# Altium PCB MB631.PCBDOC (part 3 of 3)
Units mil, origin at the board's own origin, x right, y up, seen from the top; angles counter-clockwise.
Board outline 4505 x 6805 mil, 4 copper layers (TopLayer, GND, VCC, BottomLayer); 273 components, 241 nets, 1286 pads, 636 vias.
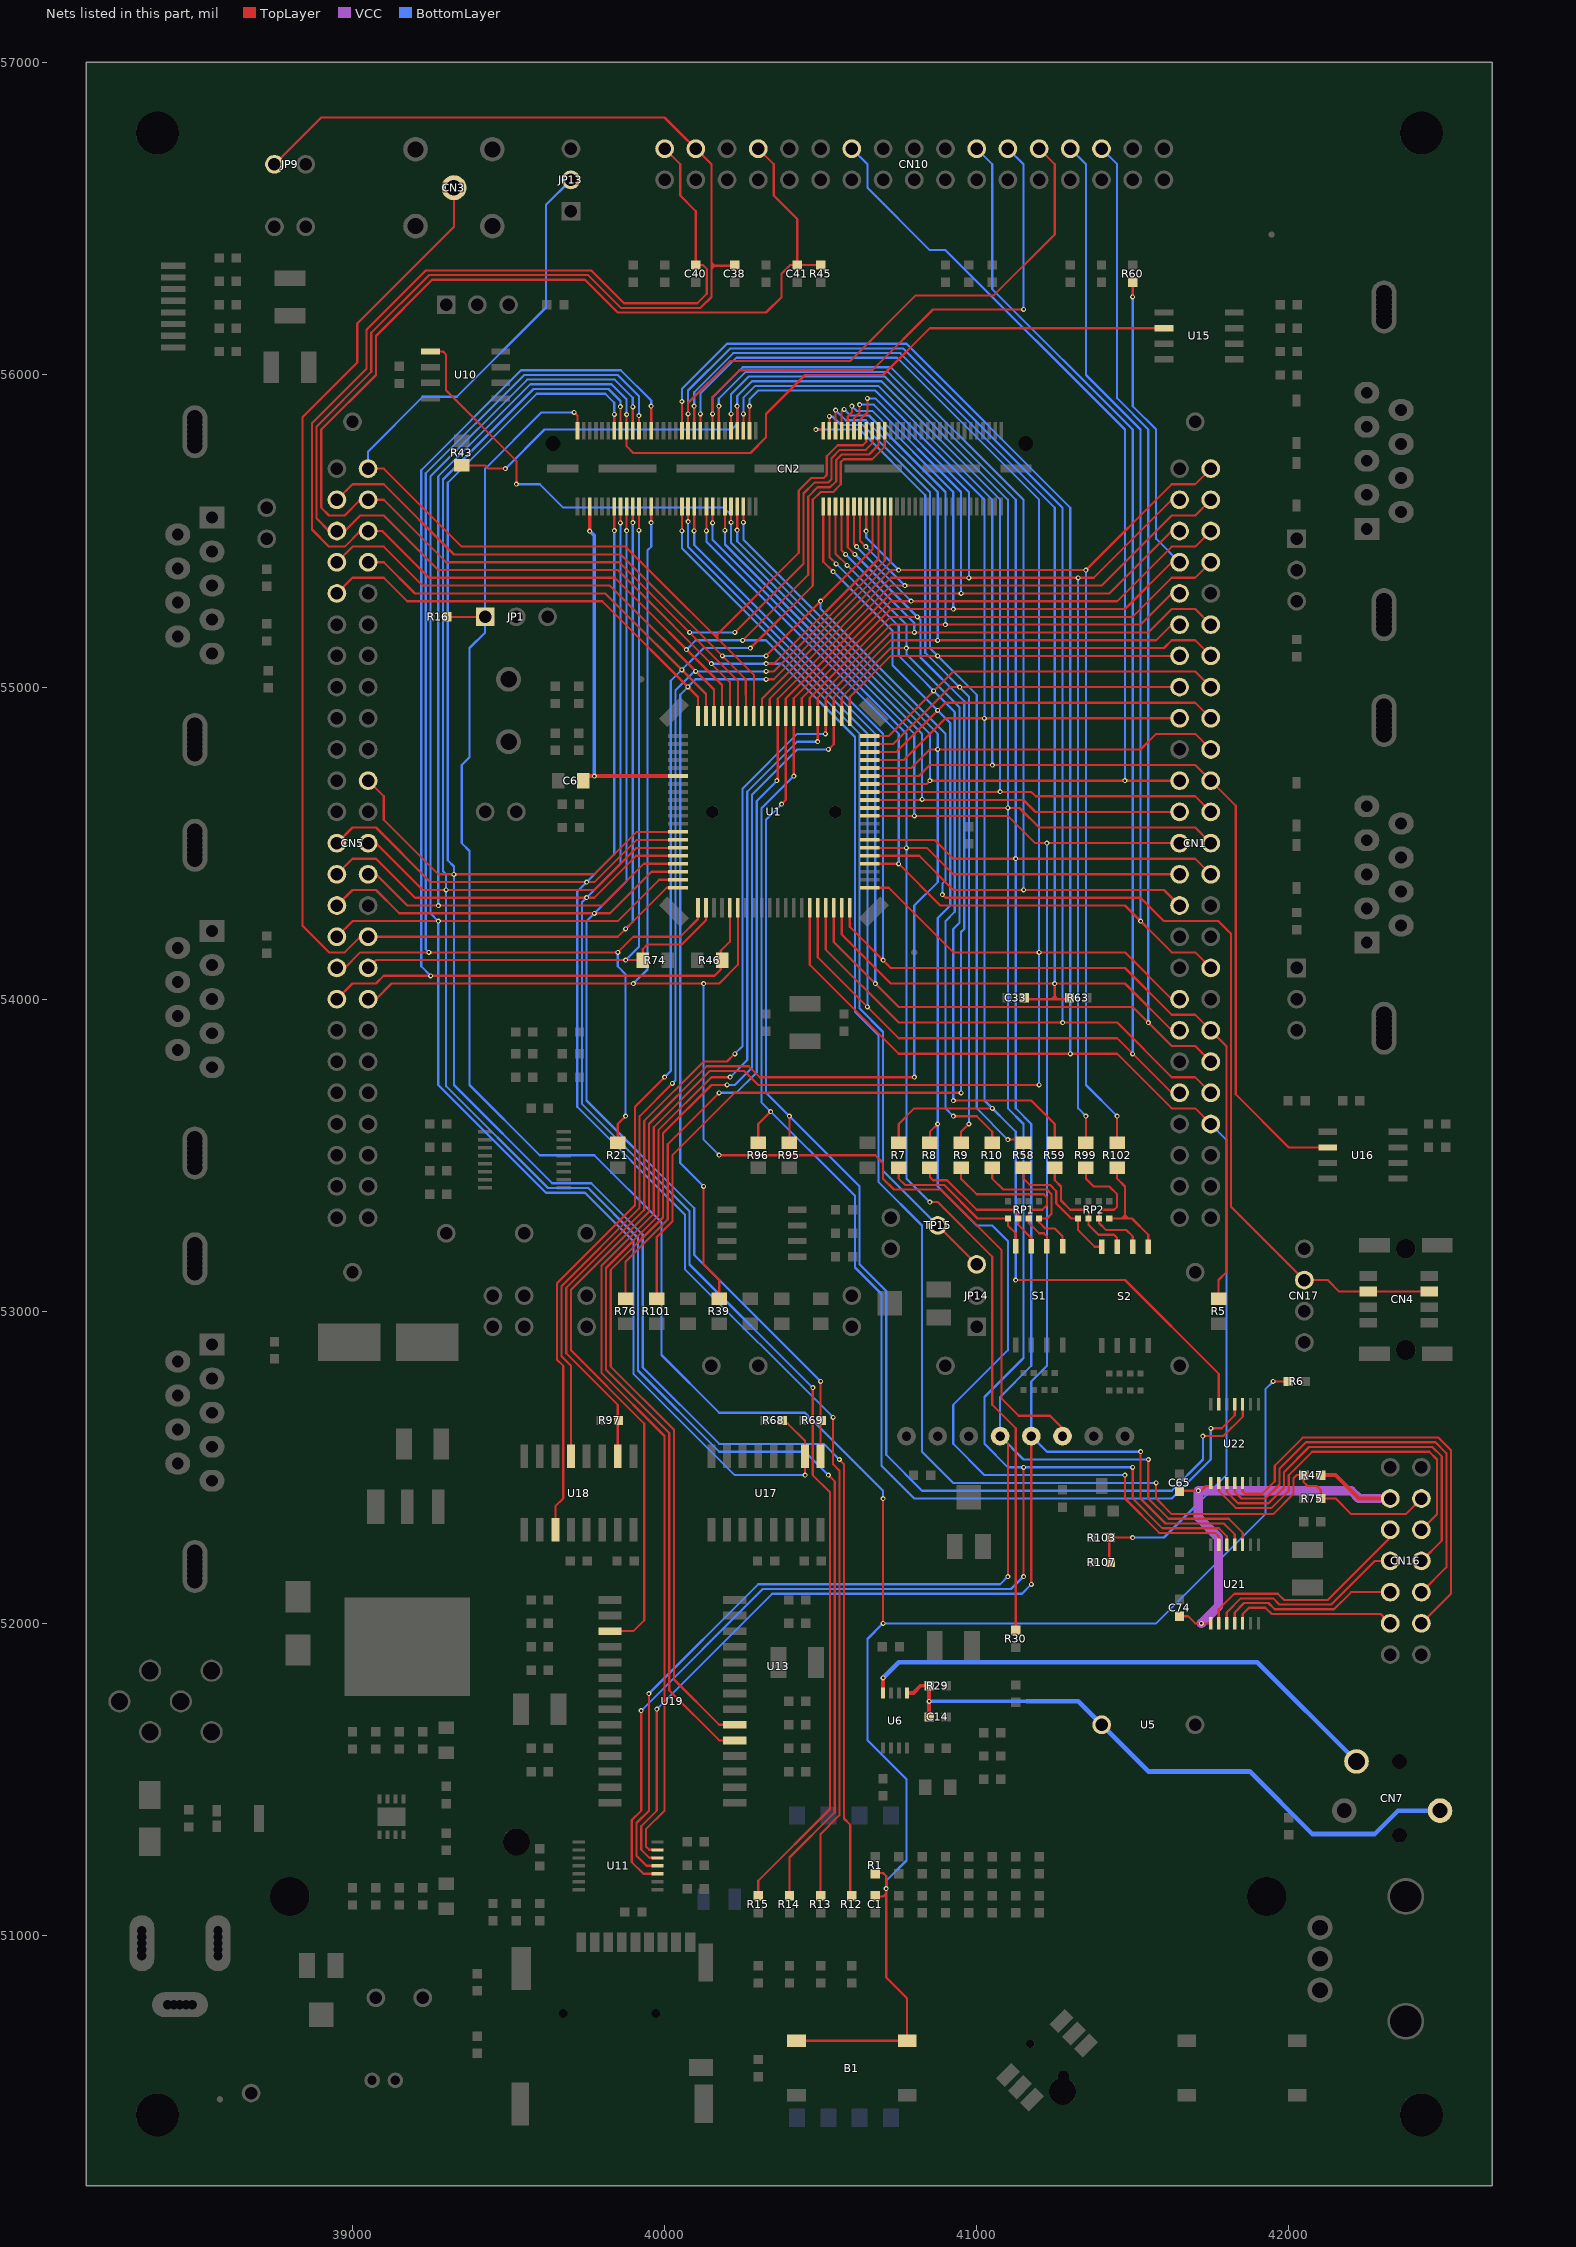
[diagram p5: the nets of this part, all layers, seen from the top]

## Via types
v1: diameter 16, hole 8, TopLayer to BottomLayer, tented both sides, 568 vias
v2: diameter 16, hole 8, TopLayer to BottomLayer, 68 vias

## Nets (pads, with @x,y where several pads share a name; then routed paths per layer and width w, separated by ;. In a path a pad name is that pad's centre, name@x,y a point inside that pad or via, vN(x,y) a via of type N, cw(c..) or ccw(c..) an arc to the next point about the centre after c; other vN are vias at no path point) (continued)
PC2: CN1.34 CN2.44 CN10.7 U1.44 | length 5197.9
  TopLayer w7: v1(40134.25,55500.75) CN2.44@40134.25,55578.54 ; U1.44@40657.09,54433.66 v1(40750,54433.66) 40883.66,54300 41475,54300 41625,54150 41700,54150 CN1.34@41750,54100
  BottomLayer w7: v1(40134.25,55500.75) 40134.25,55465.75 40750,54850 v1@40750,54435 ; CN10.7@41300,56725 41350,56675 41350,56000 41525,55825 v1(41525,54250)
PC3: CN1.29 CN2.45 CN10.11 U1.45 | length 5331
  TopLayer w7: CN2.45@40153.94,55821.46 40153.94,55930 40238.94,56015 40665,56015 40860,56210 v1(41150,56210) ; U1.45@40657.09,54459.25 40815.75,54459.25 40925,54350 41600,54350 CN1.29@41650,54300
  BottomLayer w7: v1(40153.94,55875) 40153.94,55928.94 40250,56025 40725,56025 41150,55600 v1(41150,54350) ; CN10.11@41100,56725 41150,56675 v1(41150,56210)
PC4: CN1.27 CN2.46 R30.1 U1.46 | length 5046
  TopLayer w7: v1(40153.94,55526.06) CN2.46@40153.94,55578.54 ; U1.46@40657.09,54484.84 40840.16,54484.84 40925,54400 CN1.27@41650,54400 ; v1(40850,53350) 40875,53350 41050,53175 41050,52700 41125,52625 R30.1@41125,51977.5
  BottomLayer w7: v1(40153.94,55526.06) 40153.94,55471.06 40775,54850 40775,53425 v1(40850,53350)
  other v1: 40775,54485
PC5: CN1.28 CN2.47 U1.47 U11.11 U13.4 U21.10 | length 8859.3
  TopLayer w7: v2(39950,51775) 39950,51400 39910,51360 39910,51255 39941.77,51223.23 U11.11@39976.97,51223.23 ; CN2.47@40173.62,55821.46 v1(40173.62,55900) ; U1.47@40657.09,54510.43 40864.57,54510.43 40925,54450 41700,54450 CN1.28@41750,54400 ; U13.4@41075,52600 41100,52575 v2(41100,52150) ; v2(41550,52525) 41550,52400 41615,52335 41807.36,52335 41852.36,52290 U21.10@41852.36,52251.97
  BottomLayer w7: v2(39950,51775) 40300,52125 41075,52125 v2(41100,52150) ; v1(40173.62,55900) 40173.62,55923.62 40260,56010 40715,56010 41125,55600 41125,53650 41175,53600 41175,52825 41075,52725 U13.4@41075,52600 41150,52525 v2(41550,52525)
  other v1: 41125,54450
PC6: CN1.25 CN2.50 U1.50 U11.12 U13.5 U21.11 | length 7469.7
  TopLayer w7: v2(39975,51725) 39975,51400 39925,51350 39925,51275 39951.18,51248.82 U11.12@39976.97,51248.82 ; v1(40193.31,55501.69) CN2.50@40193.31,55578.54 ; U1.50@40657.09,54587.2 41100,54587.2 41187.2,54500 CN1.25@41650,54500 ; v2(41175,52125) U13.5@41175,52600 ; v2(41525,52550) 41525,52400 41605,52320 41791.77,52320 41826.77,52285 U21.11@41826.77,52251.97
  BottomLayer w7: v2(39975,51725) 40345,52095 41145,52095 v2(41175,52125) ; v1(40193.31,55501.69) 40193.31,55456.69 40800,54850 v1(40800,54587.2) ; v1(41225,54500) 41225,52825 41175,52775 U13.5@41175,52600 41225,52550 v2(41525,52550)
PC7: CN1.26 CN2.51 U1.51 U11.10 U21.12 | length 8760.5
  TopLayer w7: v2(39925,51720) 39925,51400 39895,51370 39895,51235 39932.36,51197.64 U11.10@39976.97,51197.64 ; CN2.51@40212.99,55821.46 v1(40212.99,55875) ; U1.51@40657.09,54612.8 41137.2,54612.8 41200,54550 41700,54550 CN1.26@41750,54500 ; v2(41150,52150) v2(41150,52500) ; v2(41500,52500) 41500,52400 41595,52305 41775.59,52305 41801.18,52279.41 U21.12@41801.18,52251.97
  BottomLayer w7: v2(39925,51720) 40315,52110 41110,52110 v2(41150,52150) ; v1(40212.99,55875) 40212.99,55937.99 40270,55995 40705,55995 41100,55600 41100,53650 41150,53600 41150,52850 41025,52725 41025,52575 41100,52500 v2(41500,52500)
  other v1: 41100,54612.8
PD0: CN2.75 CN5.2 JP13.2 U1.73 | length 3859.2
  TopLayer w7: CN5.2@39050,55700 39100,55700 39350,55450 39875,55450 40286.02,55038.98 U1.73@40286.02,54907.09 ; 40154.87,55170.13 40170.13,55170.13 40170,55170 40170,55155 40169.76,55155.24 ; 40163.11,55163.11 40430,55430 40430,55630 40470,55670 40510,55670 40519.72,55679.72 40519.72,55739.72 40555,55775 40635,55775 40646.06,55786.06 CN2.75@40646.06,55821.46
  BottomLayer w7: CN5.2@39050,55700 39050,55755 39225,55930 39333.79,55930 39620,56216.21 39620,56545 JP13.2@39700,56625
PD1: CN2.78 CN4.2 CN5.3 CN17.2 U1.74 | length 6176.3
  TopLayer w7: CN5.3@38950,55600 39000,55650 39100,55650 39325,55425 39860,55425 40260,55025 40260,54975 ; U1.74@40260.43,54907.09 40260.43,54975 ; v1(40325,55100) 40665.75,55440.75 CN2.78@40665.75,55578.54 ; v1(40890,54335) 40900,54325 41525,54325 41600,54250 41775,54250 41815,54210 41815,53335 CN17.2@42050,53100 42125,53100 42162.01,53062.99 CN4.2@42449.8,53062.99
  BottomLayer w7: v1(40185,55100) v1(40325,55100) ; v1(40500,55275) 40500,55250 40900,54850 40900,54380 40890,54370 v1(40890,54335)
PD2: C41.2 CN2.77 CN5.4 CN10.27 R45.2 U1.75 | length 5464.8
  TopLayer w7: v1(40225,55175) 40445,55395 40445,55620 40480,55655 40523.79,55655 40534.72,55665.93 40534.72,55733.51 40561.21,55760 40645,55760 40665.75,55780.75 CN2.77@40665.75,55821.46 ; U1.75@40234.84,54907.09 40234.84,55020.16 39855,55400 39300,55400 39100,55600 39025,55600 38975,55550 38925,55550 38900,55575 38900,55825 39075,56000 39075,56125 39255,56305 39745,56305 39850,56200 40325,56200 40375,56250 40375,56325 40402.5,56352.5 R45.2@40500,56352.5 ; CN10.27@40300,56725 40350,56675 40350,56575 40425,56500 C41.2@40425,56352.5
  BottomLayer w7: v1(40080,55175) v1(40225,55175)
PD3: C38.2 CN2.80 CN5.5 CN10.31 CN16.11 JP9.1 R47.1 R75.2 U1.76 | length 11107.5
  TopLayer w7: JP9.1@38750,56675 38900,56825 40000,56825 40150,56675 40150,56250 40115,56215 39860,56215 39755,56320 39245,56320 39060,56135 39060,56010 38885,55835 38885,55540 38925,55500 CN5.5@38950,55500 ; CN5.5@38975,55500 39025,55550 39100,55550 39275,55375 39850,55375 40209.25,55015.75 U1.76@40209.25,54907.09 ; 40150,56340 40160,56350 40150,56360 ; 40150,56350 C38.2@40222.5,56350 ; v1(40325,55075) 40350,55075 40685.43,55410.43 CN2.80@40685.43,55578.54 ; v2(41575,52450) 41575,52400 41625,52350 41950,52350 42015,52415 42015,52465 42025,52475 R47.1@42047.5,52475 42047.5,52452.5 42060,52440 42090,52440 42102.5,52427.5 R75.2@42102.5,52400 42150,52400 42200,52350 42375,52350 CN16.11@42425,52400
  BottomLayer w7: v1(40150,55075) 40375,55075 40610,54840 40610,53960 40685,53885 40685,53415 40825,53275 40825,52550 40925,52450 v2(41575,52450)
PD4: C40.2 CN2.79 CN5.6 CN10.33 JP14.3 TP15.1 U1.77 | length 7605.7
  TopLayer w7: CN10.33@40000,56725 40050,56675 40050,56575 40100,56525 C40.2@40100,56352.5 40122.5,56352.5 40135,56340 40135,56260 40105,56230 39870,56230 39765,56335 39235,56335 39045,56145 39045,56020 38870,55845 38870,55505 38925,55450 38975,55450 39025,55500 39095,55500 39245,55350 39840,55350 40183.66,55006.34 U1.77@40183.66,54907.09 ; v1(40250,55150) 40460,55360 40460,55610 40490,55640 40530,55640 40549.72,55659.72 40549.72,55727.29 40567.43,55745 40655,55745 40685.43,55775.43 CN2.79@40685.43,55821.46 ; TP15.1@40875,53275 JP14.3@41000,53150
  BottomLayer w7: v1(40070,55120) 40100,55150 40325,55150 40625,54850 40625,53970 40700,53895 40700,53450 TP15.1@40875,53275
PD5: CN2.82 CN5.7 U1.78 U18.13 | length 5147.4
  TopLayer w7: CN5.7@38950,55400 39000,55450 39100,55450 39225,55325 39825,55325 40158.07,54991.93 U1.78@40158.07,54907.09 ; U18.13@39700,52525 39700,52825 39670,52855 39670,53081.21 39920,53331.21 39920,53625 v1(40025,53730) ; v1(40325,55050) 40350,55050 40705.12,55405.12 CN2.82@40705.12,55578.54
  BottomLayer w7: v1(40025,53730) 40035,53740 40035,54990 40095.17,55050.17 v1@40099.83,55050.17 ; v1@40100,55050 v1(40325,55050)
  other v1: 40099.49,55050.51
PD6: CN2.81 CN5.8 U1.79 U18.3 | length 5467.8
  TopLayer w7: CN5.8@39050,55400 39100,55400 39200,55300 39810,55300 40132.48,54977.52 U1.79@40132.48,54907.09 ; U18.3@39650,52300 39650,52375 39675,52400 39675,52825 39655,52845 39655,53090 39905,53340 39905,53655 v1(40000,53750) ; v1(40275,55125) 40475,55325 40475,55600 40500,55625 40540,55625 40564.72,55649.72 40564.72,55721.08 40573.64,55730 40665,55730 40705.12,55770.12 CN2.81@40705.12,55821.46
  BottomLayer w7: v1(40000,53750) 40020,53770 40020,55020 40125,55125 v1(40275,55125)
  other v1: 40055.41,55055.41
PD7: CN2.84 CN5.9 R39.2 U1.80 | length 4413.6
  TopLayer w7: CN5.9@38950,55300 39000,55350 39100,55350 39175,55275 39800,55275 40106.89,54968.11 U1.80@40106.89,54907.09 ; v1(40125,53400) 40125,53150 40175,53100 R39.2@40175,53040 ; v1(40325,55025) 40350,55025 40724.8,55399.8 CN2.84@40724.8,55578.54
  BottomLayer w7: v1(40125,53400) 40050,53475 40050,54975.81 40099.19,55025 v1(40325,55025)
  other v1: 40074.59,55000.41
PE0: CN1.4 CN2.74 R76.1 U1.70 | length 4121.2
  TopLayer w7: R76.1@39875,53040 39875,53158.93 40010,53293.93 40010,53535 v1(40175,53700) ; v1(40360,54700) 40362.8,54702.8 40362.8,54962.8 40725,55325 41400,55325 41625,55550 41700,55550 CN1.4@41750,55600 ; CN2.74@40626.38,55578.54 40626.38,55468.62 v1(40645,55450)
  BottomLayer w7: v1(40175,53700) 40230,53700 40295,53765 40295,54635 v1(40360,54700) ; v1(40645,55450) v1(40770,55325)
PE1: CN1.5 CN2.71 R95.1 U1.69 U22.10 | length 6407
  TopLayer w7: v1(40375,54625) 40388.39,54638.39 40388.39,54963.39 40725,55300 41425,55300 41625,55500 CN1.5@41650,55500 ; R95.1@40400,53540 v1(40400,53625) ; CN2.71@40606.69,55821.46 40606.69,55861.69 40625,55880 v1(40625,55905) ; v2(41725,52600) 41790,52600 41852.36,52662.36 U22.10@41852.36,52701.97
  BottomLayer w7: v1(40375,54625) 40325,54575 40325,53700 40625,53400 40625,53150 40710,53065 40710,52540 40825,52425 41625,52425 41725,52525 v2(41725,52600) ; v1(40625,55905) 40670,55905 40950,55625 v1(40950,55300)
PE2: CN1.6 CN2.72 R96.1 U1.68 U22.11 | length 6095.1
  TopLayer w7: R96.1@40300,53540 40300,53600 v1(40340,53640) ; v1(40413.98,54715) 40413.98,54963.98 40725,55275 41450,55275 41625,55450 41700,55450 CN1.6@41750,55500 ; CN2.72@40606.69,55578.54 40606.69,55458.31 v1(40615,55450) ; v2(41750,52625) 41785,52625 41826.77,52666.77 U22.11@41826.77,52701.97
  BottomLayer w7: v1(40413.98,54715) 40310,54611.02 40310,53670 40610,53370 40610,53140 40695,53055 40695,52505 40800,52400 41625,52400 41750,52525 v2(41750,52625) ; v1(40615,55450) v1(40790,55275)
PE3: CN1.7 CN2.69 R60.2 U1.67 | length 3305.7
  TopLayer w7: U1.67@40439.57,54907.09 40439.57,54964.57 40725,55250 41475,55250 41625,55400 CN1.7@41650,55400 ; CN2.69@40587.01,55821.46 40587.01,55867.01 40600,55880 v1(40600,55900) ; v1(41500,56250) R60.2@41500,56297.5
  BottomLayer w7: v1(40600,55900) 40615,55885 40665,55885 40925,55625 v1(40925,55250) ; v1(41500,56250) 41500,55900 41575,55825 41575,55475 CN1.7@41650,55400
PE4: CN1.8 CN2.70 R101.2 U1.66 | length 5048.8
  TopLayer w7: R101.2@39975,53040 39975,53237.72 40025,53287.72 40025,53500 40225,53700 v1(40950,53700) ; U1.66@40465.16,54907.09 40465.16,54965.16 40725,55225 41500,55225 41625,55350 41700,55350 CN1.8@41750,55400 ; CN2.70@40587.01,55578.54 40587.01,55447.99 v1(40610,55425)
  BottomLayer w7: v1(40610,55425) 40820,55215 40820,55095 40960,54955 40960,54225 40950,54215 v1(40950,53700)
  other v1: 40810,55225
PE5: CN1.35 CN2.41 U1.41 U11.13 | length 8308.2
  TopLayer w7: U11.13@39976.97,51274.41 39950.59,51274.41 39940,51285 39940,51340 40000,51400 40000,52600 39797.5,52802.5 39797.5,53145.07 39965,53312.57 39965,53590 40145,53770 40255,53770 40300,53725 v1(41200,53725) ; CN2.41@40114.57,55821.46 v1(40114.57,55875) ; U1.41@40657.09,54356.89 40718.11,54356.89 40925,54150 41475,54150 41625,54000 CN1.35@41650,54000
  BottomLayer w7: v1(40114.57,55875) 40114.57,55939.57 40230,56055 40745,56055 41200,55600 v1(41200,53725)
  other v1: 41200,54150
PE6: CN1.38 CN2.40 R5.1 U1.40 | length 3950.6
  TopLayer w7: v1(40094.88,55500.12) CN2.40@40094.88,55578.54 ; U1.40@40593.11,54292.91 40593.11,54231.89 40725,54100 41475,54100 41625,53950 41700,53950 41800,53850 41800,53125 41775,53100 R5.1@41775,53040
  BottomLayer w7: v1(40094.88,55500.12) 40094.88,55455.12 40700,54850 v1(40700,54125)
PE7: C33.2 CN1.37 CN2.39 R63.2 U1.39 | length 4554
  TopLayer w7: CN2.39@40094.88,55821.46 v1(40094.88,55900) ; U1.39@40567.52,54292.91 40567.52,54207.48 40725,54050 41475,54050 CN1.37@41625,53900 ; C33.2@41152.5,54000 R63.2@41297.5,54000 ; 41240,54000 41250,54010 41260,54000 ; 41250,54000 v1(41250,54050)
  BottomLayer w7: v1(40094.88,55900) 40094.88,55944.88 40220,56070 40755,56070 41250,55575 v1(41250,54050)
PF0: CN2.26 CN5.36 U1.26 U13.6 | length 5331.3
  TopLayer w7: CN5.36@39050,54000 39075,54000 39125,54050 40175,54050 40234.84,54109.84 U1.26@40234.84,54292.91 ; v1(39957.09,55527.09) CN2.26@39957.09,55578.54 ; v1(40175,53500) 40675,53500 40700,53475 40700,53425 40735,53390 40885,53390 41080,53195 41080,52720 41135,52665 41235,52665 41275,52625 U13.6@41275,52600
  BottomLayer w7: v1(39900,54050) 39945,54095 39945,55437.91 39957.09,55450 v1(39957.09,55527.09) ; v1(40125,54050) 40125,53550 v1(40175,53500)
PF1: CN2.25 CN5.35 R46.2 U1.25 | length 4118.1
  TopLayer w7: CN5.35@38950,54000 39000,54050 39075,54050 39100,54075 40160,54075 40180,54095 40180,54155 40209.25,54184.25 U1.25@40209.25,54292.91 ; CN2.25@39957.09,55821.46 v1(39957.09,55900)
  BottomLayer w7: v1(39250,54075) 39220,54105 39220,55695 39540,56015 39860,56015 39957.09,55917.91 v1(39957.09,55900)
PF2: CN2.22 CN5.34 R74.1 U1.22 | length 2677.8
  TopLayer w7: CN5.34@39050,54100 39075,54125 R74.1@39930,54125 39930,54160 39945,54175 40055,54175 40132.48,54252.48 U1.22@40132.48,54292.91 ; v1(39917.72,55502.28) CN2.22@39917.72,55578.54
  BottomLayer w7: v1(39875,54125) 39917.72,54167.72 v1(39917.72,55502.28)
PF3: CN2.21 CN5.33 R21.1 U1.21 | length 4379.8
  TopLayer w7: CN5.33@38950,54100 38975,54100 39025,54150 v1(39850,54150) 39900,54200 40050,54200 40106.89,54256.89 U1.21@40106.89,54292.91 ; R21.1@39850,53540 39850,53600 v1(39875,53625) ; CN2.21@39917.72,55821.46 v1(39917.72,55870)
  BottomLayer w7: v1(39245,54150) 39235,54160 39235,55685 39550,56000 39850,56000 39917.72,55932.28 v1(39917.72,55870) ; v1(39850,54150) 39850,54105 39875,54080 v1(39875,53625)
PF4: CN2.20 CN3.5 CN5.32 U1.20 | length 5227.8
  TopLayer w7: CN5.32@39025,54200 38975,54150 38925,54150 38840,54235 38840,55865 39015,56040 39015,56165 39325,56475 CN3.5@39325,56600 ; CN5.32@39050,54200 39850,54200 40006.89,54356.89 U1.20@40042.91,54356.89 ; v1(39898.03,55526.97) CN2.20@39898.03,55578.54
  BottomLayer w7: v1(39875,54225) 39898.03,54248.03 v1(39898.03,55526.97)
PF5: CN2.19 CN5.31 R68.2 U1.19 U17.10 | length 6179.3
  TopLayer w7: CN5.31@38950,54200 39000,54250 39850,54250 39982.48,54382.48 U1.19@40042.91,54382.48 ; CN2.19@39898.03,55821.46 v1(39898.03,55898.03) ; R68.2@40380,52640 40395,52640 40450,52585 v1(40450,52475)
  BottomLayer w7: v1(39898.03,55898.03) 39898.03,55926.97 39840,55985 39560,55985 39250,55675 39250,54275 v1(39275,54250) 39275,53725 39620,53380 39745,53380 39900,53225 39900,52800 40225,52475 v1(40450,52475)
PF6: CN2.18 CN5.29 R69.2 U1.18 U17.9 | length 4607.2
  TopLayer w7: CN5.29@38950,54300 39000,54350 39075,54350 39150,54275 39825,54275 39958.07,54408.07 U1.18@40042.91,54408.07 ; v1(39878.35,55501.65) CN2.18@39878.35,55578.54 ; U17.9@40500,52535 v1(40500,52775)
  BottomLayer w7: v1(39878.35,55501.65) 39878.35,54378.35 39750,54250 39750,53675 40095,53330 40095,53180 v1(40500,52775)
  other v1: 39775,54275
PF7: CN2.17 CN5.28 U1.17 U15.2 | length 5300.5
  TopLayer w7: CN5.28@39050,54400 39075,54400 39175,54300 39800,54300 39933.66,54433.66 U1.17@40042.91,54433.66 ; v1(39878.35,55873.35) 39878.35,55771.65 39900,55750 40275,55750 40325,55800 40325,55875 40450,56000 40700,56000 40850,56150 U15.2@41600,56150
  BottomLayer w7: v1(39275,54300) 39275,55675 39570,55970 39830,55970 39878.35,55921.65 v1(39878.35,55873.35)
PG0: CN1.23 CN2.52 U1.52 U10.1 | length 3515.8
  TopLayer w7: U10.1@39250,56075 39290,56075 39300,56065 39300,55950 39525,55725 v1(39525,55650) ; v1(40212.99,55527.99) CN2.52@40212.99,55578.54 ; U1.52@40657.09,54638.39 41150,54638.39 41188.39,54600 CN1.23@41650,54600
  BottomLayer w7: v1(39525,55650) 39600,55650 39675,55575 40190,55575 40212.99,55552.01 40212.99,55462.01 40825,54850 v1(40825,54640)
PG1: CN1.24 CN2.53 R43.2 U1.53 | length 4188.2
  TopLayer w7: R43.2@39350,55710 39425,55710 39435,55700 v1(39490,55700) ; CN2.53@40232.68,55821.46 v1(40232.68,55900) ; U1.53@40657.09,54663.98 41175,54663.98 41188.98,54650 41700,54650 CN1.24@41750,54600
  BottomLayer w7: v1(39490,55700) 39615,55825 40215,55825 40232.68,55842.68 40232.68,55932.68 40280,55980 40695,55980 41075,55600 v1(41075,54665)
PG2: CN1.21 CN2.54 CN10.21 U1.54 | length 4548.2
  TopLayer w7: v1(40232.68,55502.68) CN2.54@40232.68,55578.54 ; U1.54@40657.09,54689.57 40839.57,54689.57 v1(40850,54700) CN1.21@41650,54700
  BottomLayer w7: v1(40232.68,55502.68) 40232.68,55467.32 40850,54850 v1(40850,54700) ; CN10.21@40600,56725 40650,56675 40650,56600 40850,56400 40900,56400 41475,55825 v1(41475,54700)
PG3: CN1.22 CN2.55 U1.55 U16.2 | length 4451.9
  TopLayer w7: CN2.55@40252.36,55821.46 v1(40252.36,55875) ; U1.55@40657.09,54715.16 40815.16,54715.16 40850,54750 41700,54750 41830,54620 41830,53695 42000,53525 U16.2@42125,53525
  BottomLayer w7: v1(40252.36,55875) 40252.36,55927.36 40290,55965 40685,55965 41050,55600 v1(41050,54750)
PG4: CN1.20 CN2.56 U1.56 U19.3 | length 6132.9
  TopLayer w7: U19.3@39825,51975 39900,51975 39935,52010 39935,52640 39700,52875 39700,53068.79 39950,53318.79 39950,53600 40135,53785 40270,53785 40305,53750 v1(40800,53750) ; v1(40252.36,55527.64) CN2.56@40252.36,55578.54 ; U1.56@40657.09,54740.75 40790.75,54740.75 40850,54800 41525,54800 41575,54850 41700,54850 CN1.20@41750,54800
  BottomLayer w7: v1(40252.36,55527.64) 40252.36,55472.64 40875,54850 40875,54375 40800,54300 v1(40800,53750)
  other v1: 40875,54800
PG5: CN1.11 CN2.65 U1.63 U19.20 | length 6065.9
  TopLayer w7: v1(40200,53725) 40150,53725 39995,53570 39995,53300.15 39827.5,53132.65 39827.5,52822.5 40030,52620 40030,51820 40175,51675 U19.20@40225,51675 ; v1(40525,54800) 40541.93,54816.93 40541.93,54966.93 40725,55150 41575,55150 41625,55200 CN1.11@41650,55200 ; CN2.65@40547.64,55821.46 v1(40547.64,55887.36)
  BottomLayer w7: v1(40200,53725) 40225,53725 40280,53780 40280,54655 40425,54800 v1(40525,54800) ; v1(40547.64,55887.36) 40580,55855 40645,55855 40875,55625 v1(40875,55150)
PG6: CN1.12 CN2.68 R97.2 U1.64 U18.10 | length 4810.6
  TopLayer w7: U18.10@39850,52535 39850,52700 39685,52865 39685,53075 39935,53325 39935,53610 40125,53800 40200,53800 v1(40225,53825) ; v1@40516.34,54851.34 40516.34,54966.34 40725,55175 41550,55175 41625,55250 41700,55250 CN1.12@41750,55200 ; CN2.68@40567.32,55578.54 40567.32,55437.68 v1(40580,55425)
  BottomLayer w7: v1(40225,53825) 40250,53850 40250,54675 40425,54850 v1(40515,54850) ; v1(40580,55425) 40800,55205 v1(40800,55175)
PG7: CN1.9 CN2.67 U1.65 U19.19 | length 6123.2
  TopLayer w7: v1(40210,53750) 40150,53750 39980,53580 39980,53306.36 39812.5,53138.86 39812.5,52812.5 40015,52610 40015,51785 40175,51625 U19.19@40225,51625 ; v1@40490.75,54825.75 40490.75,54965.75 40725,55200 41525,55200 41625,55300 CN1.9@41650,55300 ; CN2.67@40567.32,55821.46 40567.32,55882.32 v1(40575,55890)
  BottomLayer w7: v1(40210,53750) 40265,53805 40265,54665 40425,54825 v1(40490,54825) ; v1(40575,55890) 40595,55870 40655,55870 40900,55625 v1(40900,55200)
PH0: CN2.13 CN5.22 R12.2 U1.13 | length 7304.8
  TopLayer w7: CN5.22@39050,54700 39100,54650 39100,54575 39275,54400 39775,54400 39911.02,54536.02 U1.13@40042.91,54536.02 ; CN2.13@39838.98,55821.46 v1(39838.98,55873.98) ; v1(40560,52525) 40575,52510 40575,51375 40595,51355 R12.2@40595,51125
  BottomLayer w7: v1(39838.98,55873.98) 39838.98,55911.02 39810,55940 39590,55940 39305,55655 39305,54445 39325,54425 39325,53725 39640,53410 39765,53410 39930,53245 39930,52820 40175,52575 40510,52575 v1(40560,52525)
  other v1: 39325,54400
PH1: CN2.14 CN5.25 R13.2 U1.14 | length 6115.3
  TopLayer w7: CN5.25@38950,54500 39000,54550 39075,54550 39250,54375 39775,54375 39910.43,54510.43 U1.14@40042.91,54510.43 ; v1(39838.98,55501.02) CN2.14@39838.98,55578.54 ; R13.2@40500,51127.5 40500,51325 40560,51385 40560,52490 40540,52510 v1(40540,52660)
  BottomLayer w7: v1(39838.98,55501.02) 39838.98,54463.98 39720,54345 39720,53655 40065,53310 40065,53135 v1(40540,52660)
  other v1: 39750,54375
PH2: CN2.15 CN5.26 R14.2 U1.15 | length 7264.5
  TopLayer w7: CN5.26@39050,54500 39075,54500 39225,54350 39775,54350 39909.84,54484.84 U1.15@40042.91,54484.84 ; CN2.15@39858.66,55821.46 v1(39858.66,55898.66) ; R14.2@40400,51127.5 40400,51250 40545,51395 40545,52455 v1(40525,52475)
  BottomLayer w7: v1(39858.66,55898.66) 39858.66,55916.34 39820,55955 39580,55955 39290,55665 39290,54410 39300,54400 39300,53721.21 39626.21,53395 39755,53395 39915,53235 39915,52810 40175,52550 40450,52550 v1(40525,52475)
  other v1: 39300,54350
PH3: CN2.16 CN5.27 R15.2 U1.16 | length 6147.8
  TopLayer w7: CN5.27@38950,54400 39000,54450 39075,54450 39200,54325 39775,54325 39909.25,54459.25 U1.16@40042.91,54459.25 ; v1(39858.66,55526.34) CN2.16@39858.66,55578.54 ; R15.2@40300,51127.5 40300,51175.01 40530,51405.01 40530,52420 40475,52475 v1(40475,52755)
  BottomLayer w7: v1(39858.66,55526.34) 39858.66,54433.66 39735,54310 39735,53665 40080,53320 40080,53150 v1(40475,52755)
  other v1: 39750,54325
PH4: CN1.44 CN2.35 R103.2 R107.2 U1.35 | length 6761.7
  TopLayer w7: v1@40055,55915 v1@40055.51,55914.49 ; CN2.35@40055.51,55821.46 v1(40055.51,55915) ; U1.35@40465.16,54292.91 40465.16,54109.84 40750,53825 41450,53825 41625,53650 41700,53650 CN1.44@41750,53600 ; R107.2@41425,52197.5 R103.2@41425,52272.5 ; R103.2@41427.5,52275 v2(41500,52275)
  BottomLayer w7: v1(40055.51,55915) 40055.51,55955.51 40200,56100 40775,56100 41300,55575 v1(41300,53825) ; v2(41500,52275) 41600,52275 41800,52475 41800,53550 CN1.44@41750,53600
PH5: CN1.41 CN2.36 CN10.13 U1.36 | length 6454.7
  TopLayer w7: v1(40055.51,55500.51) CN2.36@40055.51,55578.54 ; U1.36@40490.75,54292.91 40490.75,54134.25 40750,53875 41450,53875 41625,53700 CN1.41@41650,53700
  BottomLayer w7: v1(40055.51,55500.51) 40055.51,55444.49 40650,54850 v1(40650,53975) ; CN10.13@41000,56725 41050,56675 41050,56275 41500,55825 v1(41500,53825)
PH6: CN1.42 CN2.37 CN10.9 U1.37 | length 6532.7
  TopLayer w7: CN2.37@40075.2,55821.46 40075.2,55910 40210.2,56045 40595,56045 40805,56255 41055,56255 41250,56450 41250,56675 CN10.9@41200,56725 ; U1.37@40516.34,54292.91 40516.34,54158.66 40750,53925 41450,53925 41625,53750 41700,53750 CN1.42@41750,53700
  BottomLayer w7: v1(40075.2,55875) 40075.2,55950.2 40210,56085 40765,56085 41275,55575 v1(41275,53925)
PH7: CN1.40 CN2.38 CN10.5 U1.38 | length 6115.7
  TopLayer w7: v1(40075.2,55530.2) CN2.38@40075.2,55578.54 ; U1.38@40541.93,54292.91 40541.93,54183.07 40750,53975 41500,53975 41625,53850 41700,53850 CN1.40@41750,53800
  BottomLayer w7: v1(40075.2,55530.2) 40075.2,55449.8 40675,54850 v1(40675,54050) ; CN10.5@41400,56725 41450,56675 41450,55925 41550,55825 v1(41550,53925)
PI0: CN1.17 CN2.57 R7.2 U1.57 U22.13 | length 5853
  TopLayer w7: CN2.57@40272.05,55821.46 v1(40272.05,55900) ; U1.57@40657.09,54766.34 40766.34,54766.34 40900,54900 CN1.17@41650,54900 ; R7.2@40750,53540 40750,53600 40800,53650 v1(41050,53650) ; v2(41125,53100) 41475,53100 41775.59,52799.41 U22.13@41775.59,52701.97
  BottomLayer w7: v1(40272.05,55900) 40272.05,55922.05 40300,55950 40675,55950 41025,55600 41025,53675 41125,53575 v2(41125,53100)
  other v1: 41025,54900
PI1: CN1.18 CN2.62 R8.2 U1.58 U21.13 | length 5677.2
  TopLayer w7: CN2.62@40508.27,55578.54 40508.27,55401.73 v1(40540,55370) ; U1.58@40657.09,54791.93 40741.93,54791.93 40900,54950 41700,54950 CN1.18@41750,54900 ; R8.2@40850,53540 40850,53575 v1(40875,53600) ; v2(41475,52475) 41475,52400 41585,52290 41764.55,52290 41775.59,52278.96 U21.13@41775.59,52251.97
  BottomLayer w7: v1(40540,55370) 40730,55180 40730,55070 40915,54885 40915,54300 40875,54260 40875,53400 41000,53275 41050,53275 41100,53225 41100,52875 40925,52700 40925,52575 41025,52475 v2(41475,52475)
  other v1: 40875,54925
PI2: CN1.15 CN2.61 R9.2 U1.59 | length 3668.6
  TopLayer w7: v1(40485,55825) CN2.61@40504.72,55825 ; U1.59@40657.09,54817.52 40732.65,54817.52 40875.07,54959.93 ; 40875,54960 40915,55000 CN1.15@41650,55000 ; R9.2@40950,53540 40950,53575 v1(40975,53600)
  BottomLayer w7: v1(40485,55825) 40625,55825 40835,55615 40835,55110 40975,54970 v1(40975,53600)
  other v1: 40945,55000
PI3: CN1.16 CN2.64 R10.2 U1.60 | length 3523
  TopLayer w7: CN2.64@40527.95,55578.54 40527.95,55417.05 v1(40550,55395) ; U1.60@40657.09,54843.11 40718.11,54843.11 v1@40862.5,54987.5 ; v1(40862.36,54987.64) 40924.73,55050 41700,55050 CN1.16@41750,55000 ; v1(40925,53625) 41000,53625 41050,53575 R10.2@41050,53540
  BottomLayer w7: v1(40550,55395) 40750,55195 40750,55100 40930,54920 40930,54280 40900,54250 40900,53650 v1(40925,53625)
PI4: CN1.13 CN2.63 R58.2 U1.61 | length 3879
  TopLayer w7: CN2.63@40527.95,55821.46 v1(40527.95,55867.05) ; U1.61@40593.11,54907.09 40593.11,54968.11 40725,55100 CN1.13@41650,55100 ; v1(41100,53550) 41150,53550 R58.2@41150,53540
  BottomLayer w7: v1(40527.95,55867.05) 40537.95,55867.05 40565,55840 40635,55840 40850,55625 40850,55125 41000,54975 41000,53650 v1(41100,53550)
  other v1: 40875,55100
PI5: CN1.14 CN2.66 R59.2 U1.62 | length 3831.7
  TopLayer w7: CN2.66@40547.64,55578.54 40547.64,55427.36 v1(40585,55390) ; U1.62@40567.52,54907.09 40567.52,54967.52 40725,55125 41600,55125 41625,55150 41700,55150 CN1.14@41750,55100 ; v1(40925,53675) 41175,53675 41250,53600 R59.2@41250,53540
  BottomLayer w7: v1(40585,55390) 40775,55200 40775,55105 40945,54935 40945,54245 40925,54225 v1(40925,53675)
  other v1: 40775,55125
PI6: CN1.3 CN2.73 R99.2 U1.71 | length 4290
  TopLayer w7: U1.71@40337.2,54907.09 40337.2,54962.2 40725,55350 41375,55350 41625,55600 CN1.3@41650,55600 ; CN2.73@40626.38,55821.46 40626.38,55856.38 40650,55880 v1(40650,55925) ; R99.2@41350,53540 v1(41350,53625)
  BottomLayer w7: v1(40650,55925) 40675,55925 40975,55625 v1(40975,55350) ; v1(41325,55350) 41325,53650 v1(41350,53625)
PI7: CN1.2 CN2.76 R102.2 U1.72 | length 3921.8
  TopLayer w7: U1.72@40311.61,54907.09 40311.61,54961.61 40725,55375 v1(41350,55375) 41625,55650 41700,55650 CN1.2@41750,55700 ; v1(40646.06,55500) CN2.76@40646.06,55578.54 ; R102.2@41450,53540 v1(41450,53625)
  BottomLayer w7: v1(40646.06,55500) 40646.06,55478.94 v1(40750,55375) ; v1(41350,55375) 41350,53725 v1(41450,53625)
QST_PIN3: CN16.3 U22.5 | length 1412.9
  TopLayer w7: U22.5@41852.36,52450 41852.36,52422.64 41860,52415 41915,52415 41955,52455 41955,52505 42045,52595 42480,52595 42520,52555 42520,52095 CN16.3@42425,52000
QST_PIN4: CN16.4 U21.5 | length 531.6
  TopLayer w7: U21.5@41852.36,52000 41852.36,52030 41872.36,52050 41925,52050 41945,52030 42295,52030 CN16.4@42325,52000
QST_PIN5: CN16.5 U22.4 | length 1312
  TopLayer w7: U22.4@41826.77,52450 41826.77,52421.77 41848.54,52400 41925,52400 41970,52445 41970,52495 42055,52580 42470,52580 42505,52545 42505,52180 CN16.5@42425,52100
QST_PIN6: CN16.6 U21.4 | length 576.7
  TopLayer w7: U21.4@41826.77,52000 41826.77,52035 41856.77,52065 41935,52065 41955,52045 42145,52045 42200,52100 CN16.6@42325,52100
QST_PIN7: CN16.7 U22.3 | length 1210.8
  TopLayer w7: U22.3@41801.18,52450 41801.18,52421.18 41837.36,52385 41935,52385 41985,52435 41985,52485 42065,52565 42460,52565 42490,52535 42490,52265 CN16.7@42425,52200
QST_PIN8: CN16.8 U21.3 | length 643.7
  TopLayer w7: U21.3@41801.18,52000 41801.18,52035 41846.18,52080 41950,52080 41970,52060 42135,52060 42275,52200 CN16.8@42325,52200
QST_PIN9: CN16.9 U22.2 | length 1107.5
  TopLayer w7: U22.2@41775.59,52450 41775.59,52424.41 41830,52370 41945,52370 42000,52425 42000,52475 42075,52550 42450,52550 42475,52525 42475,52350 CN16.9@42425,52300
QST_PIN10: CN16.10 U21.2 | length 731.2
  TopLayer w7: U21.2@41775.59,52000 41775.59,52045 41825.59,52095 41965,52095 41985,52075 42125,52075 42325,52275 CN16.10@42325,52300
RESET#: B1.2 B1.3 C1.2 CN2.1 JP1.1 R1.1 R6.1 R16.2 | length 8879.5
  TopLayer w7: R16.2@39302.5,55225 JP1.1@39425,55225 ; v1(39710,55880) 39720.87,55869.13 CN2.1@39720.87,55821.46 ; B1.2@40422.83,50662.5 B1.3@40772.5,50662.5 ; C1.2@40677.5,51125 40700,51125 40710,51135 ; R1.1@40677.5,51200 40700,51200 40710,51190 40710,50865 40777.17,50797.83 B1.3@40777.17,50662.5 ; v2(40700,52000) v2(40700,52400) ; v2(41950,52775) R6.1@41997.5,52775
  BottomLayer w7: v1(39710,55880) 39605,55880 39425,55700 39425,55175 39375,55125 39375,54775 39350,54750 39350,54500 39375,54475 39375,53725 39600,53500 39775,53500 39990,53285 39990,52860 40175,52675 40450,52675 40700,52425 v2(40700,52400) ; v1(40710,51150) 40710,51175 40775,51240 40775,51500 40650,51625 40650,51950 v2(40700,52000) 41575,52000 41925,52350 41925,52750 v2(41950,52775)
SPEAKER+: CN7.2 U6.8 | length 1717
  TopLayer w12: U6.8@40700,51777.17 v1(40700,51825)
  BottomLayer w15: v1(40700,51825) 40750,51875 41899.41,51875 CN7.2@42216.93,51557.48
SPEAKER-: C14.2 CN7.1 R29.2 U5.2 U6.5 | length 2024.4
  TopLayer w12: U6.5@40776.77,51777.17 40797.17,51777.17 40820,51800 R29.2@40847.5,51800 C14.2@40847.5,51700
  BottomLayer w12: v1(40847.5,51750) 41160,51750
  BottomLayer w15: 41160,51750 41325.39,51750 41550,51525.39 41874.61,51525.39 42075,51325 42275,51325 42350,51400 CN7.1@42484.65,51400
SW0: R7.1 RP1.7 S1.2 | length 537.4
  TopLayer w7: R7.1@40750,53460 40750,53425 40770,53405 40895,53405 41002.5,53297.5 RP1.7@41100,53297.5 41100,53275 41125,53250 S1.2@41125,53208.27
SW1: R8.1 RP1.5 S1.4 | length 473
  TopLayer w7: R8.1@40850,53450 40850,53430 40860,53420 40905,53420 41000,53325 41120,53325 41133,53312 41133,53277 41175,53235 S1.4@41175,53208.27
SW2: R9.1 RP1.3 S1.6 | length 568.9
  TopLayer w7: R9.1@40950,53460 40950,53425 41000,53375 41215,53375 41225,53365 41225,53340 41210,53325 41175,53325 41167,53317 41167,53283 41200,53250 41215,53250 41225,53240 S1.6@41225,53208.27
SW3: R10.1 RP1.1 S1.8 | length 492.3
  TopLayer w7: R10.1@41050,53460 41050,53425 41085,53390 41225,53390 41240,53375 41240,53312.5 41225,53297.5 RP1.1@41200,53297.5 41200,53285 41220,53265 41250,53265 41275,53240 S1.8@41275,53208.27
SW4: R58.1 RP2.7 S2.2 | length 420.9
  TopLayer w7: R58.1@41150,53460 41150,53425 41170,53405 41235,53405 41255,53385 41255,53345 41302.5,53297.5 RP2.7@41325,53297.5 41325,53260 41378.46,53206.54 S2.2@41400,53206.54
SW5: R59.1 RP2.5 S2.4 | length 401.4
  TopLayer w7: R59.1@41250,53460 41250,53420 41270,53400 41270,53355 41300,53325 41350,53325 41358,53317 41358,53277 41390,53245 41440,53245 41450,53235 S2.4@41450,53200
SW6: R99.1 RP2.3 S2.6 | length 454.4
  TopLayer w7: R99.1@41350,53460 41350,53425 41375,53400 41425,53400 41450,53375 41450,53335 41440,53325 41400,53325 41392,53317 41392,53283 41415,53260 41480,53260 41500,53240 S2.6@41500,53206.54
SW7: R102.1 RP2.1 S2.8 | length 386.4
  TopLayer w7: RP2.1@41425,53297.5 41497.5,53297.5 41550,53245 S2.8@41550,53206.54 ; R102.1@41450,53460 41450,53425 41475,53400 41475,53297.5 ; 41465,53297.5 41475,53307.5 41485,53297.5
VCAP: C6.1 CN2.6 U1.6 | length 1173.2
  TopLayer w7: v1(39760,55500) v1@39760.24,55500.24
  TopLayer w12: C6.1@39735.16,54715.16 U1.6@40042.91,54715.16 ; v1(39760,55500) CN2.6@39760,55573.88
  BottomLayer w12: v1(39760,55500) 39775,55485 v1(39775,54715)
VDD_QST: C65.2 C74.2 CN16.12 R47.2 U21.1 U22.1 | length 1566.7
  TopLayer w7: C74.2@41650,52022.5 41677.5,52022.5 41700,52000 U21.1@41750,52000 ; C65.2@41652.5,52425 41720,52425 41735,52440 U22.1@41750,52440
  TopLayer w12: R47.2@42102.5,52475 42150,52475 42225,52400 CN16.12@42325,52400
  VCC w30: v2(41720,52000) 41775,52055 41775,52275 41710,52340 v2(41710,52425) 42200,52425 42225,52400 CN16.12@42325,52400
pads on no net: CN1.31 CN1.32 CN1.43 CN1.45 CN1.46 CN1.47 CN2.0 CN2.58 CN2.59 CN2.60 CN2.83 CN2.85 CN2.86 CN2.87 CN2.88 CN2.89 CN2.90 CN2.91 CN2.92 CN2.93 CN2.94 CN2.95 CN2.96 CN2.97 CN2.98 CN2.99 CN2.100 CN2.101 CN2.102 CN2.103 CN2.104 CN2.105 CN2.106 CN2.107 CN2.108 CN2.109 CN2.110 CN2.111 CN2.112 CN2.113 CN2.114 CN2.115 CN2.116 CN2.117 CN2.118 CN2.119 CN2.120 CN4.0 CN5.20 CN5.21 CN5.23 CN5.24 CN5.46 CN5.47 CN5.48 CN5.49 CN7.G1 CN7.G2 CN8.1 CN8.4 CN8.8 CN9.0 CN9.1 CN9.8 CN11.1 CN11.2 CN11.4 CN11.5 CN11.6 CN11.8 CN12.6 CN12.G0 CN13.9 CN14.1 CN14.2 CN14.4 CN14.5 CN14.6 CN14.8 CN15.9 U1.0 U7. U9.0 U10.5 U11.6 U11.9 U13.0 U14.2 U15.8 U16.8 U17.2 U18.2 U18.4 U18.11 U18.15 U19.10 U19.25 U21.6 U21.9 U22.6 U22.9
copper on no net: | length 12020
  TopLayer w5: 38150,54550 38275,54550 ; 38150,54675 38275,54675 38400,54675 ; 38150,54800 38275,54800 38400,54800 ; 38255,54550 38400,54550 ; 38275,54300 38275,54425 ; 38275,55050 38275,54925 ; 38150,54425 38150,54925 ; 38150,54425 38275,54425 ; 38150,54425 38150,54300 38400,54300 38400,54425 ; 38150,54925 38275,54925 ; 38150,54925 38150,55050 38395,55050 38400,55050 38400,54925 ; 38275,54425 38400,54425 ; 38275,54425 38275,54925 ; 38275,54925 38400,54925 ; 38400,54425 38400,54925
  VCC w5: 38150,54425 38400,54425 ; 38150,54550 38400,54550 ; 38150,54675 38400,54675 ; 38150,54800 38400,54800 ; 38150,54925 38400,54925 ; 38275,54300 38275,55050 ; 38150,54300 38400,54300 38400,55050 38150,55050 38150,54300
  BottomLayer w5: 38150,54550 38275,54550 38400,54550 ; 38150,54675 38275,54675 38400,54675 ; 38150,54800 38275,54800 38400,54800 ; 38275,54300 38275,54425 ; 38275,55050 38275,54925 ; 38150,54425 38150,54925 ; 38150,54425 38275,54425 ; 38150,54425 38150,54300 38400,54300 38400,54425 ; 38150,54925 38275,54925 ; 38150,54925 38150,55050 38400,55050 38400,54925 ; 38275,54425 38400,54425 ; 38275,54425 38275,54925 ; 38275,54925 38400,54925 ; 38400,54425 38400,54925

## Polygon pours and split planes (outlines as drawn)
GND on TopLayer (hatched 90Degree grid 20 track 10, remove dead copper): 38145,57000 42645,57000 42645,50200 38145,50200
E5V on VCC (hatched 90Degree grid 10 track 10, remove dead copper): 38150,51725 38825,51725 38825,52325 39150,52650 39450,52650 39575,52775 39575,52990 39492.75,52990 39450,52947.25 39400,52897.25 38150,52897.25
D5V on VCC (hatched 90Degree grid 10 track 10, remove dead copper): 38150,54825 39050,54825 39050,53025 39575,53025 39650,53100 41350,53100 41600,53350 41700,53350 41700,52925 41575,52800 38150,52800
+5V_MCU on VCC (hatched 90Degree grid 10 track 10, remove dead copper): 39475,54625 39475,55825 40700,55825 40900,55625 40900,54075 40720,53895 40700,53875 40550,53875 40455,53970 40455,54050 40105,54400 39475,54400
+5V_VDDA on VCC (hatched 90Degree grid 10 track 10, remove dead copper): 40040,54400 40200,54400 40565,54035 40810,54035 40865,54090 40865,55620 40670,55815 39800,55815 39800,56050 40850,56050 41200,55700 41200,53700 40025,53700 40025,54400
+3V3 on VCC (hatched 90Degree grid 10 track 10, remove dead copper): 39125,52775 39495,52775 39570,52850 41530,52850 41700,53020 41700,55850 40740,55850 40640,55950 40540,56050 39050,56050 38850,55850 38850,55100 38550,55100 38550,55900 38850,56200 38875,56225 40150,56225 40150,56675 40450,56675 40450,56225 41950,56225 41950,52625 39675,52625 39350,52300 39125,52300
+5V on VCC (hatched 90Degree grid 10 track 10, remove dead copper): 38150,57000 42650,57000 42650,50200 38150,50200
VDD_QST on VCC (hatched 90Degree grid 10 track 10, remove dead copper): 41650,52455 42380,52455 42380,51950 41675,51950 41675,52125 41750,52200 41750,52275 41650,52375
GND on BottomLayer (hatched 90Degree grid 20 track 10, remove dead copper): 38150,57000 42650,57000 42650,50200 38150,50200

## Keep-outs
KeepOutLayer:
  lines w4: 38150,54300 38150,54425 38150,54925
  lines w5: 38150,50200 39425,50200 39450,50225 39450,50300 39475,50325 40175,50325 40200,50300 40200,50225 40225,50200 42650,50200 42650,57000 38150,57000 38150,50200

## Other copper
TopLayer:
  text "1" at 38250,54475 h50 r90
  text "D" at 38360,54465 h50 r90
VCC:
  text "3" at 38250,54760 h50 r90
  text "D" at 38360,54760 h50 r90
BottomLayer:
  text "4" at 38250,54885 h50 r90
  text "D" at 38360,54885 h50 r90
GND (plane layer: these items are gaps in the copper):
  region: 38425,54280 38425,54550 38125,54550 38125,54280
  region: 38425,54550 38425,54675 38400,54675 38400,54550
  region: 38150,54550 38150,54675 38125,54675 38125,54550
  rectangle: 38125,54675 38425,55075
  lines w4: 38150,54300 38150,54425 ; 38150,54550 38270,54550 ; 38150,54675 38275,54675 38400,54675 ; 38150,54800 38275,54800 38400,54800 ; 38270,54425 38275,54425 ; 38275,54300 38275,54425 ; 38275,54550 38400,54550 ; 38400,54300 38400,54425 ; 38150,54425 38150,54925 38275,54925 ; 38150,54425 38275,54425 ; 38275,54425 38400,54425 ; 38275,54425 38275,54925 ; 38275,54925 38400,54925 38400,54425
  text "2" at 38250,54595 h50 r90
  text "D" at 38360,54595 h50 r90

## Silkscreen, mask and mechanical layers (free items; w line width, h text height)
TopOverlay:
  drawing of 4241 lines, arcs and shapes, not listed
  text "MOTOR_CTL" at 40500,56895 h60
  text "1" at 41590,56870 h40
  text "AIN12" at 38995,56775 h40
  text "IrDA" at 38300,56475 h60
  text "1" at 39695,56420 h40
  text "LIN1" at 42275,56375 h60
  text "CAN MODE" at 39250,56285 h40
  text "1" at 39200,56200 h40
  text "CAN" at 38335,55960 h60
  text "STice" at 40250,55925 h60
  text "GND" at 41770,55825 h40
  text "GND" at 39055,55820 h40
  text "1" at 41625,55765 h40
  text "2" at 41750,55765 h40
  text "1" at 38925,55760 h40
  text "2" at 39025,55760 h40
  text "GND" at 38780,55695 h40
  text "PD0" at 39115,55675 h40
  text "GND" at 41475,55675 h40
  text "PI7" at 41815,55675 h40
  text "TERMINAL" at 38665,55640 h35
  text "PD2" at 39115,55575 h40
  text "PI6" at 41485,55575 h40
  text "PE0" at 41815,55575 h40
  text "PD1" at 38790,55570 h40
  text "1" at 41975,55540 h40
  text "PD4" at 39115,55475 h40
  text "PE1" at 41485,55475 h40
  text "PE2" at 41815,55475 h40
  text "1" at 42110,55475 h40
  text "PD3" at 38800,55465 h40
  text "PD5" at 38790,55375 h40
  text "PD6" at 39115,55375 h40
  text "PE3" at 41490,55375 h40
  text "PE4" at 41815,55375 h40
  text "ALONE" at 39350,55300 h40
  text "STice" at 39565,55300 h40
  text "D" at 41228,55293 h30
  text "GND" at 39115,55280 h40
  text "PG7" at 41490,55275 h40
  text "GND" at 41815,55275 h40
  text "1" at 39340,55200 h40
  text "RST" at 38790,55175 h40
  text "PA0" at 39115,55175 h40
  text "PG5" at 41490,55175 h40
  text "PG6" at 41815,55175 h40
  text "PA2" at 38790,55075 h40
  text "PA1" at 39115,55075 h40
  text "PI4" at 41490,55075 h40
  text "PI5" at 41815,55075 h40
  text "LIN2" at 42280,55030 h60
  text "PA4" at 38790,54975 h40
  text "PA3" at 39115,54975 h40
  text "PI2" at 41490,54975 h40
  text "PI3" at 41815,54975 h40
  text "PA6" at 38790,54875 h40
  text "PA5" at 39115,54875 h40
  text "PI0" at 41490,54875 h40
  text "PI1" at 41815,54875 h40
  text "pin1" at 39820,54845 h40
  text "D5V" at 38790,54775 h40
  text "GND" at 41490,54775 h40
  text "PG4" at 41815,54775 h40
  text "PH0" at 39115,54675 h40
  text "PG2" at 41490,54675 h40
  text "PG3" at 41815,54675 h40
  text "USART1" at 38415,54625 h60
  text "PG0" at 41490,54575 h40
  text "PG1" at 41815,54575 h40
  text "PH1" at 38790,54475 h40
  text "PH2" at 39115,54475 h40
  text "PC6" at 41490,54475 h40
  text "PC7" at 41815,54475 h40
  text "5V MCU" at 39350,54470 h50
  text "PH3" at 38790,54375 h40
  text "PF7" at 39115,54375 h40
  text "PC4" at 41490,54375 h40
  text "PC5" at 41815,54375 h40
  text "D" at 38360,54350 h50 r90
  text "S" at 38250,54345 h50 r90
  text "PF6" at 38785,54275 h40
  text "GND" at 39115,54275 h40
  text "PC3" at 41490,54275 h40
  text "GND" at 41815,54275 h40
  text "1" at 38675,54175 h40
  text "PF5" at 38785,54175 h40
  text "PF4" at 39115,54175 h40
  text "1" at 41975,54160 h40
  text "1" at 42115,54150 h40
  text "PF3" at 38785,54075 h40
  text "PF2" at 39115,54075 h40
  text "PC1" at 41490,54075 h40
  text "PC2" at 41815,54075 h40
  text "PF1" at 38785,53975 h40
  text "PF0" at 39115,53975 h40
  text "PE5" at 41490,53975 h40
  text "PC0" at 41815,53975 h40
  text "PB7" at 38785,53875 h40
  text "PB6" at 39115,53875 h40
  text "PE7" at 41490,53875 h40
  text "PE6" at 41815,53875 h40
  text "GND" at 38785,53775 h40
  text "PB5" at 39115,53775 h40
  text "GND" at 41490,53775 h40
  text "PH7" at 41820,53775 h40
  text "PB4" at 38785,53675 h40
  text "PB3" at 39115,53675 h40
  text "PH5" at 41490,53675 h40
  text "PH6" at 41820,53675 h40
  text "PB2" at 38785,53575 h40
  text "PB1" at 39115,53575 h40
  text "PH4" at 41820,53575 h40
  text "PB0" at 38785,53475 h40
  text "3V3" at 41825,53375 h40
  text "E2P WP" at 40635,53365 h40
  text "USART2" at 38365,53305 h60
  text "D5V" at 41490,53275 h40
  text "GND" at 41825,53275 h40
  text "GND" at 39110,53265 h40
  text "5V" at 39415,53230 h40
  text "MIC" at 39610,53225 h40
  text "49" at 38925,53200 h40
  text "50" at 39025,53200 h40
  text "49" at 41625,53200 h40
  text "50" at 41725,53200 h40
  text "1" at 41910,53180 h40
  text "POWER_SEL" at 39400,53125 h40
  text "1" at 42175,53100 h40
  text "3V3" at 39250,53095 h40
  text "GND" at 41755,53090 h40
  text "GND" at 39065,53085 h40
  text "SWIM" at 42610,52940 h60 r90
  text "1" at 38665,52850 h40
  text "DTB" at 39400,52850 h40
  text "PSU" at 39520,52850 h40
  text "1" at 40990,52840 h40
  text "Speaker" at 40635,52825 h40
  text "PSU: Power Supply Unit" at 39295,52780 h36
  text "AUX2" at 40340,52735 h40
  text "AUX1" at 40180,52730 h40
  text "3V3" at 41720,52725 h40
  text "DTB: Daughter Board power source" at 39295,52720 h36
  text "Audio" at 40750,52715 h40
  text "QST" at 42630,52125 h60 r90
  text "1" at 42590,51875 h40
  text "Audio JACK" at 42100,51620 h60
  text "DC5V" at 38430,51180 h50
  text "PSU" at 38185,51175 h60
  text "PH3 . . PH0" at 40285,50950 h40
  text "MIC+" at 39020,50855 h40
  text "MIC-" at 39175,50855 h40
  text "Mic" at 38685,50730 h40
  text "PC0" at 41890,50720 h40
  text "-" at 38570,50670 h50
  text "+" at 38305,50665 h50
  text "AIN8" at 42150,50580 h60
  text "GND" at 38680,50549.77 h40
  text "MSD" at 39285,50440 h60
  text "Microphone" at 38810,50400 h50
BottomOverlay:
  drawing of 728 lines, arcs and shapes, not listed
  text "D" at 41030,55980 h40
  text "B" at 38250,55000 h50 r90
  text "D" at 38360,55000 h50 r90
  text "Smart Card" at 40815,51600 h40
  text "NC" at 40400,51450 h40 r270
  text "CLK" at 40500,51450 h40 r270
  text "RST" at 40600,51450 h40 r270
  text "VCC" at 40700,51450 h40 r270
  text "NC" at 40400,50250 h40 r270
  text "I/O" at 40500,50250 h40 r270
  text "NC" at 40600,50250 h40 r270
  text "GND" at 40700,50250 h40 r270
Mechanical1:
  lines w5: 38150,50200 39425,50200 39450,50225 39450,50300 39475,50325 40175,50325 40200,50300 40200,50225 40225,50200 42650,50200 42650,57000 38150,57000 38150,50200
